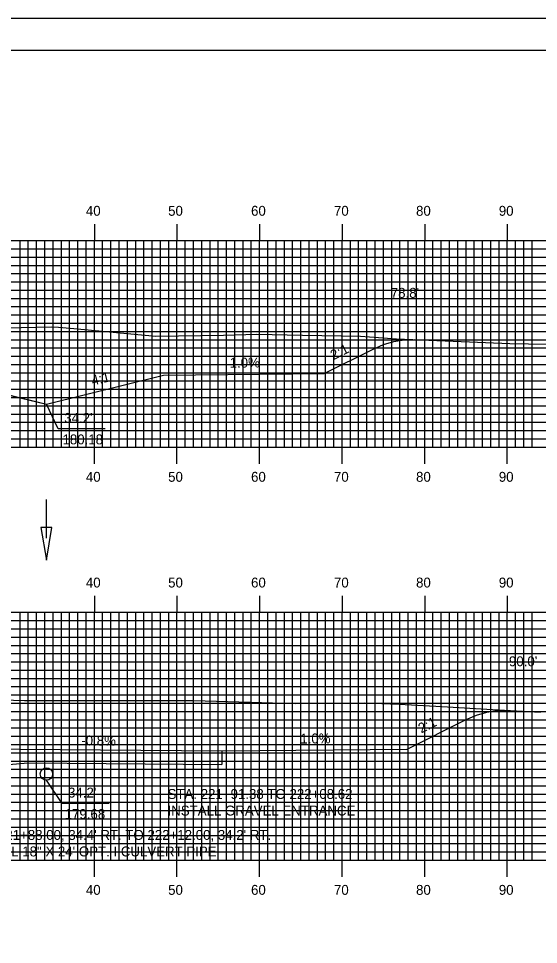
# Model space of a CAD drawing. Extents: x 1797207 to 1797550, y 442591 to 442811.
# Drawn here: x 1797403.7 to 1797466.7, y 442698.5 to 442810.5 of the extents above; entities that cross this region are included whole.
import ezdxf

# ---------------------------------------------------------------- set-up
doc = ezdxf.new("R2010")
doc.units = 0
for name, color, linetype in [('ANNOTATION', 7, 'Continuous'), ('BORDER', 7, 'Continuous'), ('D_Drainage_Ditch_Line', 7, 'Continuous'), ('D_Roadway_Centerline', 7, 'Continuous'), ('D_Roadway_SlopeLines', 7, 'Continuous'), ('D_Roadway_SubGrade', 7, 'Continuous'), ('D_Text_Standard', 7, 'Continuous'), ('H_V ANNOTATION', 7, 'Continuous'), ('MAJOR', 7, 'Continuous'), ('MINOR', 7, 'Continuous'), ('PLOT BOUNDARY', 7, 'Continuous'), ('S_Roadway_Centerline', 7, 'Continuous')]:
    doc.layers.add(name, color=color, linetype=linetype)

msp = doc.modelspace()

# ---------------------------------------------------------------- linework, layer by layer
at = {"layer": 'ANNOTATION'}
for points in [[(1797414.23, 442760.87), (1797408.54, 442760.87), (1797407.11, 442763.85)], [(1797414.7, 442715.52), (1797409.01, 442715.52), (1797407.11, 442718.35)]]:
    msp.add_lwpolyline(points, dxfattribs=at)
at = {"layer": 'BORDER'}
msp.add_lwpolyline([(1797223.33, 442596.67), (1797543.33, 442596.67), (1797543.33, 442806.67), (1797223.33, 442806.67)], close=True, dxfattribs=at)
at = {"layer": 'D_Drainage_Ditch_Line'}
msp.add_line((1797407.11, 442747.63), (1797407.11, 442752.33), dxfattribs=at)
msp.add_lwpolyline([(1797407.76, 442748.94), (1797406.45, 442748.94), (1797407.11, 442745)], close=True, dxfattribs=at)
at = {"layer": 'D_Roadway_Centerline'}
for points in [[(1797294.18, 442774.92), (1797295.43, 442774.81), (1797296.68, 442774.55), (1797297.93, 442774.15), (1797299.18, 442773.6), (1797310.36, 442768.01), (1797324.58, 442767.87), (1797338.76, 442764.33), (1797342.76, 442765.33), (1797352.93, 442767.87), (1797360.93, 442768.19), (1797372.93, 442767.95), (1797384.93, 442767.71), (1797392.93, 442767.39), (1797403.11, 442764.85), (1797407.11, 442763.85), (1797421.28, 442767.39), (1797440.76, 442767.58), (1797446.68, 442770.54), (1797447.93, 442771.08), (1797449.18, 442771.45), (1797450.43, 442771.65), (1797451.68, 442771.68)], [(1797428.37, 442721.89), (1797450.8, 442722.11), (1797457.93, 442725.68), (1797459.18, 442726.22), (1797460.43, 442726.58), (1797461.68, 442726.78), (1797462.93, 442726.8)]]:
    msp.add_lwpolyline(points, dxfattribs=at)
at = {"layer": 'D_Roadway_SlopeLines'}
for points in [[(1797421.28, 442767.39), (1797440.76, 442767.58), (1797446.68, 442770.54), (1797447.93, 442771.08), (1797449.18, 442771.45), (1797450.43, 442771.65), (1797451.68, 442771.68)], [(1797392.93, 442767.39), (1797407.11, 442763.85)], [(1797407.11, 442763.85), (1797421.28, 442767.39)], [(1797428.37, 442721.89), (1797450.8, 442722.11), (1797457.93, 442725.68), (1797459.18, 442726.22), (1797460.43, 442726.58), (1797461.68, 442726.78), (1797462.93, 442726.8)]]:
    msp.add_lwpolyline(points, dxfattribs=at)
at = {"layer": 'D_Roadway_SubGrade'}
for p in [(1797428.37, 442721.89), (1797419.07, 442720.34)]:
    msp.add_line(p, (1797428.37, 442720.26), dxfattribs=at)
for points in [[(1797392.93, 442721.89), (1797398.93, 442722.13), (1797428.37, 442721.89)], [(1797393.43, 442719.54), (1797393.93, 442719.53), (1797404.93, 442720.46), (1797419.07, 442720.34)]]:
    msp.add_lwpolyline(points, dxfattribs=at)
msp.add_circle((1797407.12, 442719.1), 0.75, dxfattribs=at)
at = {"layer": 'MAJOR'}
for p, q in [((1797412.93, 442785.67), (1797412.93, 442783.67)), ((1797422.93, 442785.67), (1797422.93, 442783.67)), ((1797432.93, 442785.67), (1797432.93, 442783.67)), ((1797442.93, 442785.67), (1797442.93, 442783.67)), ((1797452.93, 442785.67), (1797452.93, 442783.67)), ((1797462.93, 442785.67), (1797462.93, 442783.67)), ((1797232.93, 442783.67), (1797512.93, 442783.67)), ((1797232.93, 442783.67), (1797512.93, 442783.67)), ((1797412.93, 442758.67), (1797412.93, 442783.67)), ((1797422.93, 442758.67), (1797422.93, 442783.67)), ((1797432.93, 442758.67), (1797432.93, 442783.67)), ((1797442.93, 442758.67), (1797442.93, 442783.67)), ((1797452.93, 442758.67), (1797452.93, 442783.67)), ((1797462.93, 442758.67), (1797462.93, 442783.67)), ((1797232.93, 442778.67), (1797512.93, 442778.67)), ((1797232.93, 442773.67), (1797512.93, 442773.67)), ((1797232.93, 442768.67), (1797512.93, 442768.67)), ((1797232.93, 442763.67), (1797512.93, 442763.67)), ((1797232.93, 442758.67), (1797512.93, 442758.67)), ((1797232.93, 442758.67), (1797512.93, 442758.67)), ((1797412.93, 442756.66), (1797412.93, 442758.67)), ((1797422.93, 442756.66), (1797422.93, 442758.67)), ((1797432.93, 442756.66), (1797432.93, 442758.67)), ((1797442.93, 442756.66), (1797442.93, 442758.67)), ((1797452.93, 442756.66), (1797452.93, 442758.67)), ((1797462.93, 442756.66), (1797462.93, 442758.67)), ((1797412.93, 442740.67), (1797412.93, 442738.67)), ((1797422.93, 442740.67), (1797422.93, 442738.67)), ((1797432.93, 442740.67), (1797432.93, 442738.67)), ((1797442.93, 442740.67), (1797442.93, 442738.67)), ((1797452.93, 442740.67), (1797452.93, 442738.67)), ((1797462.93, 442740.67), (1797462.93, 442738.67)), ((1797232.93, 442738.67), (1797512.93, 442738.67)), ((1797232.93, 442738.67), (1797512.93, 442738.67)), ((1797412.93, 442708.67), (1797412.93, 442738.67)), ((1797422.93, 442708.67), (1797422.93, 442738.67)), ((1797432.93, 442708.67), (1797432.93, 442738.67)), ((1797442.93, 442708.67), (1797442.93, 442738.67)), ((1797452.93, 442708.67), (1797452.93, 442738.67)), ((1797462.93, 442708.67), (1797462.93, 442738.67)), ((1797232.93, 442733.67), (1797512.93, 442733.67)), ((1797232.93, 442728.67), (1797512.93, 442728.67)), ((1797232.93, 442723.67), (1797512.93, 442723.67)), ((1797232.93, 442718.67), (1797512.93, 442718.67)), ((1797232.93, 442713.67), (1797512.93, 442713.67)), ((1797232.93, 442708.67), (1797512.93, 442708.67)), ((1797232.93, 442708.67), (1797512.93, 442708.67)), ((1797412.93, 442706.66), (1797412.93, 442708.67)), ((1797422.93, 442706.66), (1797422.93, 442708.67)), ((1797432.93, 442706.66), (1797432.93, 442708.67)), ((1797442.93, 442706.66), (1797442.93, 442708.67)), ((1797452.93, 442706.66), (1797452.93, 442708.67)), ((1797462.93, 442706.66), (1797462.93, 442708.67))]:
    msp.add_line(p, q, dxfattribs=at)
at = {"layer": 'MINOR'}
for p, q in [((1797403.93, 442758.67), (1797403.93, 442783.67)), ((1797404.93, 442758.67), (1797404.93, 442783.67)), ((1797405.93, 442758.67), (1797405.93, 442783.67)), ((1797406.93, 442758.67), (1797406.93, 442783.67)), ((1797407.93, 442758.67), (1797407.93, 442783.67)), ((1797408.93, 442758.67), (1797408.93, 442783.67)), ((1797409.93, 442758.67), (1797409.93, 442783.67)), ((1797410.93, 442758.67), (1797410.93, 442783.67)), ((1797411.93, 442758.67), (1797411.93, 442783.67)), ((1797413.93, 442758.67), (1797413.93, 442783.67)), ((1797414.93, 442758.67), (1797414.93, 442783.67)), ((1797415.93, 442758.67), (1797415.93, 442783.67)), ((1797416.93, 442758.67), (1797416.93, 442783.67)), ((1797417.93, 442758.67), (1797417.93, 442783.67)), ((1797418.93, 442758.67), (1797418.93, 442783.67)), ((1797419.93, 442758.67), (1797419.93, 442783.67)), ((1797420.93, 442758.67), (1797420.93, 442783.67)), ((1797421.93, 442758.67), (1797421.93, 442783.67)), ((1797423.93, 442758.67), (1797423.93, 442783.67)), ((1797424.93, 442758.67), (1797424.93, 442783.67)), ((1797425.93, 442758.67), (1797425.93, 442783.67)), ((1797426.93, 442758.67), (1797426.93, 442783.67)), ((1797427.93, 442758.67), (1797427.93, 442783.67)), ((1797428.93, 442758.67), (1797428.93, 442783.67)), ((1797429.93, 442758.67), (1797429.93, 442783.67)), ((1797430.93, 442758.67), (1797430.93, 442783.67)), ((1797431.93, 442758.67), (1797431.93, 442783.67)), ((1797433.93, 442758.67), (1797433.93, 442783.67)), ((1797434.93, 442758.67), (1797434.93, 442783.67)), ((1797435.93, 442758.67), (1797435.93, 442783.67)), ((1797436.93, 442758.67), (1797436.93, 442783.67)), ((1797437.93, 442758.67), (1797437.93, 442783.67)), ((1797438.93, 442758.67), (1797438.93, 442783.67)), ((1797439.93, 442758.67), (1797439.93, 442783.67)), ((1797440.93, 442758.67), (1797440.93, 442783.67)), ((1797441.93, 442758.67), (1797441.93, 442783.67)), ((1797443.93, 442758.67), (1797443.93, 442783.67)), ((1797444.93, 442758.67), (1797444.93, 442783.67)), ((1797445.93, 442758.67), (1797445.93, 442783.67)), ((1797446.93, 442758.67), (1797446.93, 442783.67)), ((1797447.93, 442758.67), (1797447.93, 442783.67)), ((1797448.93, 442758.67), (1797448.93, 442783.67)), ((1797449.93, 442758.67), (1797449.93, 442783.67)), ((1797450.93, 442758.67), (1797450.93, 442783.67)), ((1797451.93, 442758.67), (1797451.93, 442783.67)), ((1797453.93, 442758.67), (1797453.93, 442783.67)), ((1797454.93, 442758.67), (1797454.93, 442783.67)), ((1797455.93, 442758.67), (1797455.93, 442783.67)), ((1797456.93, 442758.67), (1797456.93, 442783.67)), ((1797457.93, 442758.67), (1797457.93, 442783.67)), ((1797458.93, 442758.67), (1797458.93, 442783.67)), ((1797459.93, 442758.67), (1797459.93, 442783.67)), ((1797460.93, 442758.67), (1797460.93, 442783.67)), ((1797461.93, 442758.67), (1797461.93, 442783.67)), ((1797463.93, 442758.67), (1797463.93, 442783.67)), ((1797464.93, 442758.67), (1797464.93, 442783.67)), ((1797465.93, 442758.67), (1797465.93, 442783.67)), ((1797232.93, 442782.67), (1797512.93, 442782.67)), ((1797232.93, 442781.67), (1797512.93, 442781.67)), ((1797232.93, 442780.67), (1797512.93, 442780.67)), ((1797232.93, 442779.67), (1797512.93, 442779.67)), ((1797232.93, 442777.67), (1797512.93, 442777.67)), ((1797232.93, 442776.67), (1797512.93, 442776.67)), ((1797232.93, 442775.67), (1797512.93, 442775.67)), ((1797232.93, 442774.67), (1797512.93, 442774.67)), ((1797232.93, 442772.67), (1797512.93, 442772.67)), ((1797232.93, 442771.67), (1797512.93, 442771.67)), ((1797232.93, 442770.67), (1797512.93, 442770.67)), ((1797232.93, 442769.67), (1797512.93, 442769.67)), ((1797232.93, 442767.67), (1797512.93, 442767.67)), ((1797232.93, 442766.67), (1797512.93, 442766.67)), ((1797232.93, 442765.67), (1797512.93, 442765.67)), ((1797232.93, 442764.67), (1797512.93, 442764.67)), ((1797232.93, 442762.67), (1797512.93, 442762.67)), ((1797232.93, 442761.67), (1797512.93, 442761.67)), ((1797232.93, 442760.67), (1797512.93, 442760.67)), ((1797232.93, 442759.67), (1797512.93, 442759.67)), ((1797403.93, 442708.67), (1797403.93, 442738.67)), ((1797404.93, 442708.67), (1797404.93, 442738.67)), ((1797405.93, 442708.67), (1797405.93, 442738.67)), ((1797406.93, 442708.67), (1797406.93, 442738.67)), ((1797407.93, 442708.67), (1797407.93, 442738.67)), ((1797408.93, 442708.67), (1797408.93, 442738.67)), ((1797409.93, 442708.67), (1797409.93, 442738.67)), ((1797410.93, 442708.67), (1797410.93, 442738.67)), ((1797411.93, 442708.67), (1797411.93, 442738.67)), ((1797413.93, 442708.67), (1797413.93, 442738.67)), ((1797414.93, 442708.67), (1797414.93, 442738.67)), ((1797415.93, 442708.67), (1797415.93, 442738.67)), ((1797416.93, 442708.67), (1797416.93, 442738.67)), ((1797417.93, 442708.67), (1797417.93, 442738.67)), ((1797418.93, 442708.67), (1797418.93, 442738.67)), ((1797419.93, 442708.67), (1797419.93, 442738.67)), ((1797420.93, 442708.67), (1797420.93, 442738.67)), ((1797421.93, 442708.67), (1797421.93, 442738.67)), ((1797423.93, 442708.67), (1797423.93, 442738.67)), ((1797424.93, 442708.67), (1797424.93, 442738.67)), ((1797425.93, 442708.67), (1797425.93, 442738.67)), ((1797426.93, 442708.67), (1797426.93, 442738.67)), ((1797427.93, 442708.67), (1797427.93, 442738.67)), ((1797428.93, 442708.67), (1797428.93, 442738.67)), ((1797429.93, 442708.67), (1797429.93, 442738.67)), ((1797430.93, 442708.67), (1797430.93, 442738.67)), ((1797431.93, 442708.67), (1797431.93, 442738.67)), ((1797433.93, 442708.67), (1797433.93, 442738.67)), ((1797434.93, 442708.67), (1797434.93, 442738.67)), ((1797435.93, 442708.67), (1797435.93, 442738.67)), ((1797436.93, 442708.67), (1797436.93, 442738.67)), ((1797437.93, 442708.67), (1797437.93, 442738.67)), ((1797438.93, 442708.67), (1797438.93, 442738.67)), ((1797439.93, 442708.67), (1797439.93, 442738.67)), ((1797440.93, 442708.67), (1797440.93, 442738.67)), ((1797441.93, 442708.67), (1797441.93, 442738.67)), ((1797443.93, 442708.67), (1797443.93, 442738.67)), ((1797444.93, 442708.67), (1797444.93, 442738.67)), ((1797445.93, 442708.67), (1797445.93, 442738.67)), ((1797446.93, 442708.67), (1797446.93, 442738.67)), ((1797447.93, 442708.67), (1797447.93, 442738.67)), ((1797448.93, 442708.67), (1797448.93, 442738.67)), ((1797449.93, 442708.67), (1797449.93, 442738.67)), ((1797450.93, 442708.67), (1797450.93, 442738.67)), ((1797451.93, 442708.67), (1797451.93, 442738.67)), ((1797453.93, 442708.67), (1797453.93, 442738.67)), ((1797454.93, 442708.67), (1797454.93, 442738.67)), ((1797455.93, 442708.67), (1797455.93, 442738.67)), ((1797456.93, 442708.67), (1797456.93, 442738.67)), ((1797457.93, 442708.67), (1797457.93, 442738.67)), ((1797458.93, 442708.67), (1797458.93, 442738.67)), ((1797459.93, 442708.67), (1797459.93, 442738.67)), ((1797460.93, 442708.67), (1797460.93, 442738.67)), ((1797461.93, 442708.67), (1797461.93, 442738.67)), ((1797463.93, 442708.67), (1797463.93, 442738.67)), ((1797464.93, 442708.67), (1797464.93, 442738.67)), ((1797465.93, 442708.67), (1797465.93, 442738.67)), ((1797232.93, 442737.67), (1797512.93, 442737.67)), ((1797232.93, 442736.67), (1797512.93, 442736.67)), ((1797232.93, 442735.67), (1797512.93, 442735.67)), ((1797232.93, 442734.67), (1797512.93, 442734.67)), ((1797232.93, 442732.67), (1797512.93, 442732.67)), ((1797232.93, 442731.67), (1797512.93, 442731.67)), ((1797232.93, 442730.67), (1797512.93, 442730.67)), ((1797232.93, 442729.67), (1797512.93, 442729.67)), ((1797232.93, 442727.67), (1797512.93, 442727.67)), ((1797232.93, 442726.67), (1797512.93, 442726.67)), ((1797232.93, 442725.67), (1797512.93, 442725.67)), ((1797232.93, 442724.67), (1797512.93, 442724.67)), ((1797232.93, 442722.67), (1797512.93, 442722.67)), ((1797232.93, 442721.67), (1797512.93, 442721.67)), ((1797232.93, 442720.67), (1797512.93, 442720.67)), ((1797232.93, 442719.67), (1797512.93, 442719.67)), ((1797232.93, 442717.67), (1797512.93, 442717.67)), ((1797232.93, 442716.67), (1797512.93, 442716.67)), ((1797232.93, 442715.67), (1797512.93, 442715.67)), ((1797232.93, 442714.67), (1797512.93, 442714.67)), ((1797232.93, 442712.67), (1797512.93, 442712.67)), ((1797232.93, 442711.67), (1797512.93, 442711.67)), ((1797232.93, 442710.67), (1797512.93, 442710.67)), ((1797232.93, 442709.67), (1797512.93, 442709.67))]:
    msp.add_line(p, q, dxfattribs=at)
at = {"layer": 'PLOT BOUNDARY'}
msp.add_lwpolyline([(1797207.14, 442590.55), (1797547.14, 442590.55), (1797547.14, 442810.55), (1797207.14, 442810.55)], close=True, dxfattribs=at)
at = {"layer": 'S_Roadway_Centerline'}
for points in [[(1797338.85, 442773.76), (1797346.65, 442773.7), (1797356.94, 442773.88), (1797366.43, 442773.72), (1797369.5, 442773.89), (1797376.5, 442773.61), (1797382.61, 442773.17), (1797388.07, 442772.81), (1797402.23, 442773.12), (1797407.7, 442773.21), (1797408.6, 442773.19), (1797410.01, 442773.08), (1797420.37, 442772.1), (1797428.58, 442772.22), (1797432.61, 442772.33), (1797438.13, 442772.23), (1797445.15, 442772.08), (1797449.51, 442771.77), (1797463.24, 442771.2), (1797470.07, 442771.1)], [(1797331.86, 442730.14), (1797343.1, 442729.66), (1797343.99, 442729.62), (1797345.24, 442729.58), (1797363.56, 442729.09), (1797366.97, 442729), (1797371.3, 442728.84), (1797378.9, 442728.53), (1797383.95, 442728.67), (1797390.15, 442728.68), (1797400.45, 442728.11), (1797404.48, 442727.99), (1797422.18, 442727.99), (1797424.47, 442727.99), (1797424.67, 442728), (1797424.96, 442728), (1797437.25, 442727.65), (1797445.58, 442727.73), (1797449.83, 442727.56), (1797455.01, 442727.25), (1797461.14, 442726.89), (1797466.94, 442726.6)]]:
    msp.add_lwpolyline(points, dxfattribs=at)

# ---------------------------------------------------------------- texts
at = {"layer": 'ANNOTATION'}
for s, rotation, p in [('2:1', 26.5651, (1797441.87, 442769.17)), ('1.0%', 0.5729, (1797429.31, 442768.27)), ('4:1', 14.0364, (1797412.73, 442766.11)), ('2:1', 26.5651, (1797452.51, 442724)), ('-0.8%', 359.5328, (1797411.34, 442722.56)), ('1.0%', 0.5729, (1797437.87, 442722.78))]:
    msp.add_text(s, height=1.2, rotation=rotation, dxfattribs=at).set_placement(p)
for s, p in [("34.2'", (1797409.28, 442761.6)), ('180.18', (1797409.07, 442759)), ("34.2'", (1797409.74, 442716.25)), ('STA. 221+91.38 TO 222+08.62', (1797421.79, 442716.08)), ('179.68', (1797409.33, 442713.65)), ('INSTALL GRAVEL ENTRANCE', (1797421.79, 442714.07)), ("STA. 221+88.00, 34.4' RT. TO 222+12.00, 34.2' RT.", (1797397.24, 442711.12)), ('INSTALL 18" X 24\' OPT. I CULVERT PIPE', (1797397.24, 442709.12))]:
    msp.add_text(s, height=1.2, dxfattribs=at).set_placement(p)
at = {"layer": 'D_Text_Standard'}
for s, p in [("78.8'", (1797448.82, 442776.74)), ("90.0'", (1797463.13, 442732.14))]:
    msp.add_text(s, height=1.2, dxfattribs=at).set_placement(p)
at = {"layer": 'H_V ANNOTATION'}
for s, p in [('40', (1797411.9, 442786.67)), ('50', (1797421.86, 442786.67)), ('60', (1797431.9, 442786.67)), ('70', (1797441.94, 442786.67)), ('80', (1797451.88, 442786.67)), ('90', (1797461.9, 442786.67)), ('40', (1797411.9, 442754.47)), ('50', (1797421.86, 442754.47)), ('60', (1797431.9, 442754.47)), ('70', (1797441.94, 442754.47)), ('80', (1797451.88, 442754.47)), ('90', (1797461.9, 442754.47)), ('40', (1797411.9, 442741.67)), ('50', (1797421.86, 442741.67)), ('60', (1797431.9, 442741.67)), ('70', (1797441.94, 442741.67)), ('80', (1797451.88, 442741.67)), ('90', (1797461.9, 442741.67)), ('40', (1797411.9, 442704.47)), ('50', (1797421.86, 442704.47)), ('60', (1797431.9, 442704.47)), ('70', (1797441.94, 442704.47)), ('80', (1797451.88, 442704.47)), ('90', (1797461.9, 442704.47))]:
    msp.add_text(s, height=1.2, dxfattribs=at).set_placement(p)

doc.saveas('drawing.dxf')
